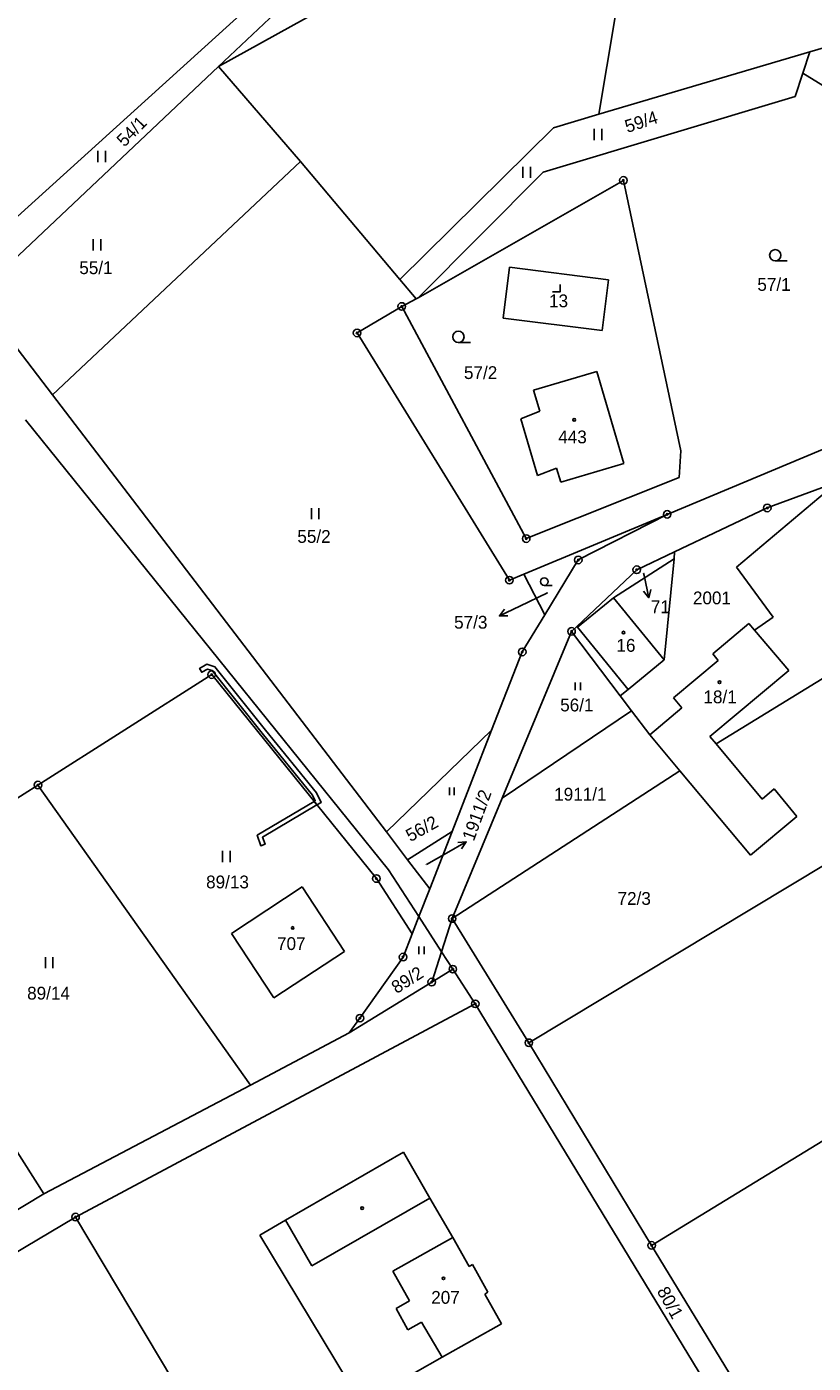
# Model space of a CAD drawing. Extents: x -445050 to -440454, y -1134563 to -1129741.
# Drawn here: x -441462.8 to -441358.3, y -1130247.4 to -1130069.9 of the extents above; entities that cross this region are included whole.
import ezdxf

# ---------------------------------------------------------------- set-up
doc = ezdxf.new("R2010")
doc.units = 0
for name, color, linetype in [('Vrstva 1', 7, 'Continuous'), ('Vrstva 16', 7, 'Continuous'), ('Vrstva 18', 7, 'Continuous'), ('Vrstva 19', 7, 'Continuous'), ('Vrstva 24', 7, 'Continuous'), ('Vrstva 25', 7, 'Continuous'), ('Vrstva 3', 7, 'Continuous'), ('Vrstva 30', 7, 'Continuous'), ('Vrstva 37', 7, 'Continuous'), ('Vrstva 4', 7, 'Continuous'), ('Vrstva 6', 7, 'Continuous')]:
    doc.layers.add(name, color=color, linetype=linetype)

msp = doc.modelspace()

# ---------------------------------------------------------------- linework, layer by layer
at = {"layer": 'Vrstva 1'}
for p, q in [((-441461.32, -1130170.56), (-441438.25, -1130155.89)), ((-441438.25, -1130155.89), (-441416.37, -1130182.98)), ((-441485.35, -1130185.84), (-441461.32, -1130170.56)), ((-441433.11, -1130210.4), (-441461.32, -1130170.56)), ((-441416.37, -1130182.98), (-441411.63, -1130190.33)), ((-441435.6, -1130190.26), (-441426.21, -1130184.1)), ((-441426.21, -1130184.1), (-441420.61, -1130192.66)), ((-441410.73, -1130188.03), (-441411.63, -1130190.33)), ((-441429.99, -1130198.8), (-441435.6, -1130190.26)), ((-441411.63, -1130190.33), (-441412.83, -1130193.4)), ((-441420.61, -1130192.66), (-441429.99, -1130198.8)), ((-441419.98, -1130203.47), (-441433.11, -1130210.4)), ((-441433.11, -1130210.4), (-441460.53, -1130224.86))]:
    msp.add_line(p, q, dxfattribs=at)
for points in [[(-441360.76, -1130079.1), (-441359.72, -1130076)], [(-441359.72, -1130076), (-441341.25, -1130087.41)], [(-441394.23, -1130089.18), (-441360.76, -1130079.1)], [(-441394.23, -1130089.18), (-441410.83, -1130105.86)], [(-441410.83, -1130105.86), (-441383.57, -1130090.26)], [(-441383.57, -1130090.26), (-441375.92, -1130126.16)], [(-441399.55, -1130108.54), (-441398.7, -1130101.8)], [(-441398.7, -1130101.8), (-441385.55, -1130103.45)], [(-441385.55, -1130103.45), (-441386.39, -1130110.19)], [(-441469.51, -1130105.5), (-441459.4, -1130118.73)], [(-441418.94, -1130110.52), (-441413.01, -1130107)], [(-441413.01, -1130107), (-441411.07, -1130105.99)], [(-441413.01, -1130107), (-441396.47, -1130137.84)], [(-441411.07, -1130105.99), (-441410.83, -1130105.86)], [(-441386.39, -1130110.19), (-441399.55, -1130108.54)], [(-441398.71, -1130143.35), (-441418.94, -1130110.52)], [(-441387.1, -1130115.63), (-441395.52, -1130118.1)], [(-441383.51, -1130127.88), (-441387.1, -1130115.63)], [(-441395.52, -1130118.1), (-441394.68, -1130120.93)], [(-441459.4, -1130118.73), (-441415.04, -1130176.77)], [(-441394.68, -1130120.93), (-441397.19, -1130121.93)], [(-441462.97, -1130122.08), (-441414.75, -1130181.81)], [(-441397.19, -1130121.93), (-441394.98, -1130129.46)], [(-441377.75, -1130134.61), (-441351.39, -1130123.59)], [(-441375.92, -1130126.16), (-441376.15, -1130129.73)], [(-441394.98, -1130129.46), (-441392.45, -1130128.47)], [(-441392.45, -1130128.47), (-441391.88, -1130130.32)], [(-441391.88, -1130130.32), (-441383.51, -1130127.88)], [(-441376.15, -1130129.73), (-441396.47, -1130137.84)], [(-441355.09, -1130130.3), (-441368.53, -1130141.61)], [(-441355.09, -1130130.3), (-441364.45, -1130133.76)], [(-441376.78, -1130139.6), (-441364.45, -1130133.76)], [(-441318.92, -1130132.99), (-441371.23, -1130165.11)], [(-441377.75, -1130134.61), (-441396.77, -1130142.54)], [(-441389.56, -1130140.67), (-441377.75, -1130134.61)], [(-441393.99, -1130147.95), (-441389.56, -1130140.67)], [(-441384.88, -1130145.69), (-441376.84, -1130140.52)], [(-441376.78, -1130139.6), (-441381.8, -1130141.97)], [(-441378.14, -1130153.94), (-441376.84, -1130140.52)], [(-441376.78, -1130139.6), (-441376.84, -1130140.52)], [(-441396.77, -1130142.54), (-441398.71, -1130143.35)], [(-441396.77, -1130142.54), (-441393.99, -1130147.95)], [(-441381.8, -1130141.97), (-441389.76, -1130149.5)], [(-441368.53, -1130141.61), (-441363.66, -1130148.25)], [(-441389.67, -1130149.61), (-441384.88, -1130145.69)], [(-441397, -1130152.88), (-441393.99, -1130147.95)], [(-441363.66, -1130148.25), (-441366.15, -1130150.01)], [(-441390.45, -1130150.15), (-441399.66, -1130172.29)], [(-441389.76, -1130149.5), (-441390.45, -1130150.15)], [(-441390.45, -1130150.15), (-441383.98, -1130158.72)], [(-441389.67, -1130149.61), (-441389.76, -1130149.5)], [(-441371.68, -1130153.14), (-441366.91, -1130149.12)], [(-441366.91, -1130149.12), (-441366.15, -1130150.01)], [(-441366.15, -1130150.01), (-441361.6, -1130155.35)], [(-441401.07, -1130163.29), (-441397, -1130152.88)], [(-441370.99, -1130154), (-441371.68, -1130153.14)], [(-441378.14, -1130153.94), (-441382.93, -1130157.86)], [(-441376.91, -1130158.99), (-441370.99, -1130154)], [(-441361.6, -1130155.35), (-441372.07, -1130164.1)], [(-441383.98, -1130158.72), (-441382.93, -1130157.86)], [(-441382.47, -1130160.71), (-441383.98, -1130158.72)], [(-441375.79, -1130160.32), (-441376.91, -1130158.99)], [(-441382.47, -1130160.71), (-441399.66, -1130172.29)], [(-441380.07, -1130163.89), (-441382.47, -1130160.71)], [(-441380.07, -1130163.89), (-441375.79, -1130160.32)], [(-441415.04, -1130176.77), (-441401.07, -1130163.29)], [(-441406.32, -1130176.73), (-441401.07, -1130163.29)], [(-441376.07, -1130168.66), (-441380.07, -1130163.89)], [(-441372.07, -1130164.1), (-441371.23, -1130165.11)], [(-441371.23, -1130165.11), (-441365.15, -1130172.43)], [(-441376.07, -1130168.66), (-441406.31, -1130188.29)], [(-441366.69, -1130179.87), (-441376.07, -1130168.66)], [(-441365.15, -1130172.43), (-441363.53, -1130171.07)], [(-441363.53, -1130171.07), (-441360.51, -1130174.73)], [(-441399.66, -1130172.29), (-441406.31, -1130188.29)], [(-441360.51, -1130174.73), (-441366.69, -1130179.87)], [(-441415.04, -1130176.77), (-441412.22, -1130180.49)], [(-441406.32, -1130176.73), (-441412.22, -1130180.49)], [(-441409.29, -1130184.35), (-441406.32, -1130176.73)], [(-441410.73, -1130188.03), (-441414.75, -1130181.81)], [(-441412.22, -1130180.49), (-441409.29, -1130184.35)], [(-441410.73, -1130188.03), (-441409.29, -1130184.35)], [(-441460.53, -1130224.86), (-441485.35, -1130185.84)], [(-441410.73, -1130188.03), (-441407.72, -1130192.69)], [(-441406.31, -1130188.29), (-441407.72, -1130192.69)], [(-441406.31, -1130188.29), (-441396.12, -1130204.79)], [(-441407.72, -1130192.69), (-441406.22, -1130195.01)], [(-441418.56, -1130201.52), (-441412.83, -1130193.4)], [(-441406.22, -1130195.01), (-441409.02, -1130196.73)], [(-441403.24, -1130199.62), (-441406.22, -1130195.01)], [(-441409.02, -1130196.73), (-441419.98, -1130203.47)], [(-441403.24, -1130199.62), (-441456.33, -1130227.93)], [(-441403.24, -1130199.62), (-441353.13, -1130282.09)], [(-441418.56, -1130201.52), (-441419.98, -1130203.47)], [(-441379.81, -1130231.69), (-441396.12, -1130204.79)], [(-441412.78, -1130219.31), (-441428.46, -1130228.36)], [(-441409.26, -1130225.41), (-441412.78, -1130219.31)], [(-441460.53, -1130224.86), (-441465.68, -1130227.95)], [(-441409.26, -1130225.41), (-441406.23, -1130230.65)], [(-441456.33, -1130227.93), (-441507.09, -1130258.08)], [(-441456.33, -1130227.93), (-441408.04, -1130308.81)], [(-441428.46, -1130228.36), (-441431.87, -1130230.33)], [(-441431.87, -1130230.33), (-441418.41, -1130252.66)], [(-441406.23, -1130230.65), (-441404.06, -1130234.5)], [(-441379.81, -1130231.69), (-441350.11, -1130280.47)], [(-441404.06, -1130234.5), (-441403.62, -1130234.25)], [(-441403.62, -1130234.25), (-441401.55, -1130237.93)], [(-441401.55, -1130237.93), (-441401.98, -1130238.17)], [(-441401.98, -1130238.17), (-441399.76, -1130242.11)], [(-441399.76, -1130242.11), (-441407.63, -1130246.56)], [(-441407.63, -1130246.56), (-441418.41, -1130252.66)]]:
    msp.add_lwpolyline(points, dxfattribs=at)
at = {"layer": 'Vrstva 16'}
for p, q in [((-441380.81, -1130142.75), (-441380.18, -1130145.68)), ((-441397.32, -1130146.79), (-441400.03, -1130148.09)), ((-441407.04, -1130179.59), (-441404.43, -1130178.11))]:
    msp.add_line(p, q, dxfattribs=at)
for points in [[(-441380.88, -1130142.42), (-441380.81, -1130142.75)], [(-441379.9, -1130144.6), (-441380.18, -1130145.68), (-441380.88, -1130144.81)], [(-441393.66, -1130145.04), (-441397.32, -1130146.79)], [(-441398.91, -1130148.1), (-441400.03, -1130148.09), (-441399.34, -1130147.2)], [(-441405.55, -1130178.17), (-441404.43, -1130178.11), (-441405.05, -1130179.04)], [(-441409.72, -1130181.12), (-441407.04, -1130179.59)]]:
    msp.add_lwpolyline(points, dxfattribs=at)
at = {"layer": 'Vrstva 24'}
for centre, radius in [((-441383.57, -1130090.26), 0.5), ((-441383.57, -1130090.26), 0.1), ((-441413.01, -1130107), 0.5), ((-441413.01, -1130107), 0.1), ((-441418.94, -1130110.52), 0.5), ((-441418.94, -1130110.52), 0.1), ((-441377.75, -1130134.61), 0.5), ((-441364.45, -1130133.76), 0.5), ((-441364.45, -1130133.76), 0.1), ((-441377.75, -1130134.61), 0.1), ((-441396.47, -1130137.84), 0.5), ((-441396.47, -1130137.84), 0.1), ((-441389.56, -1130140.67), 0.5), ((-441389.56, -1130140.67), 0.1), ((-441398.71, -1130143.35), 0.5), ((-441381.8, -1130141.97), 0.5), ((-441381.8, -1130141.97), 0.1), ((-441398.71, -1130143.35), 0.1), ((-441390.45, -1130150.15), 0.5), ((-441390.45, -1130150.15), 0.1), ((-441397, -1130152.88), 0.5), ((-441397, -1130152.88), 0.1), ((-441438.25, -1130155.89), 0.5), ((-441438.25, -1130155.89), 0.1), ((-441461.32, -1130170.56), 0.5), ((-441461.32, -1130170.56), 0.1), ((-441416.37, -1130182.98), 0.5), ((-441416.37, -1130182.98), 0.1), ((-441406.31, -1130188.29), 0.5), ((-441406.31, -1130188.29), 0.1), ((-441412.83, -1130193.4), 0.5), ((-441412.83, -1130193.4), 0.1), ((-441406.22, -1130195.01), 0.5), ((-441409.02, -1130196.73), 0.5), ((-441406.22, -1130195.01), 0.1), ((-441409.02, -1130196.73), 0.1), ((-441403.24, -1130199.62), 0.5), ((-441403.24, -1130199.62), 0.1), ((-441418.56, -1130201.52), 0.5), ((-441418.56, -1130201.52), 0.1), ((-441396.12, -1130204.79), 0.5), ((-441396.12, -1130204.79), 0.1), ((-441456.33, -1130227.93), 0.5), ((-441456.33, -1130227.93), 0.1), ((-441379.81, -1130231.69), 0.5), ((-441379.81, -1130231.69), 0.1)]:
    msp.add_circle(centre, radius, dxfattribs=at)
at = {"layer": 'Vrstva 25'}
for p, q in [((-441387.44, -1130084.93), (-441387.44, -1130083.43)), ((-441386.44, -1130084.93), (-441386.44, -1130083.43)), ((-441453.35, -1130087.83), (-441453.35, -1130086.33)), ((-441452.35, -1130087.83), (-441452.35, -1130086.33)), ((-441396.9, -1130089.94), (-441396.9, -1130088.44)), ((-441395.9, -1130089.94), (-441395.9, -1130088.44)), ((-441453.97, -1130099.57), (-441453.97, -1130098.07)), ((-441452.97, -1130099.57), (-441452.97, -1130098.07)), ((-441363.4, -1130100.95), (-441361.8, -1130100.95)), ((-441405.48, -1130111.79), (-441403.88, -1130111.79)), ((-441425.01, -1130135.27), (-441425.01, -1130133.77)), ((-441424.01, -1130135.27), (-441424.01, -1130133.77)), ((-441394.08, -1130144.05), (-441393.01, -1130144.05)), ((-441389.95, -1130157.96), (-441389.95, -1130156.96)), ((-441389.28, -1130157.96), (-441389.28, -1130156.96)), ((-441406.68, -1130171.89), (-441406.68, -1130170.89)), ((-441406.02, -1130171.89), (-441406.02, -1130170.89)), ((-441436.8, -1130180.82), (-441436.8, -1130179.32)), ((-441435.8, -1130180.82), (-441435.8, -1130179.32)), ((-441410.72, -1130193.01), (-441410.72, -1130192.01)), ((-441410.04, -1130193.01), (-441410.04, -1130192.01)), ((-441460.34, -1130194.9), (-441460.34, -1130193.4)), ((-441459.34, -1130194.9), (-441459.34, -1130193.4))]:
    msp.add_line(p, q, dxfattribs=at)
msp.add_lwpolyline([(-441392.97, -1130105.08), (-441391.97, -1130105.08), (-441391.97, -1130104.08)], dxfattribs=at)
for centre, radius in [((-441363.4, -1130100.2), 0.75), ((-441405.48, -1130111.04), 0.75), ((-441390.09, -1130122.06), 0.175), ((-441394.08, -1130143.55), 0.503), ((-441383.54, -1130150.32), 0.175), ((-441370.79, -1130156.91), 0.175), ((-441427.49, -1130189.54), 0.175), ((-441418.27, -1130226.75), 0.175), ((-441407.45, -1130236.07), 0.175)]:
    msp.add_circle(centre, radius, dxfattribs=at)
at = {"layer": 'Vrstva 3'}
for points in [[(-441387.1, -1130115.63), (-441395.52, -1130118.1)], [(-441383.51, -1130127.88), (-441387.1, -1130115.63)], [(-441395.52, -1130118.1), (-441394.68, -1130120.93)], [(-441394.68, -1130120.93), (-441397.19, -1130121.93)], [(-441397.19, -1130121.93), (-441394.98, -1130129.46)], [(-441394.98, -1130129.46), (-441392.45, -1130128.47)], [(-441392.45, -1130128.47), (-441391.88, -1130130.32)], [(-441391.88, -1130130.32), (-441383.51, -1130127.88)], [(-441389.67, -1130149.61), (-441384.88, -1130145.69)], [(-441384.88, -1130145.69), (-441378.14, -1130153.94)], [(-441382.93, -1130157.86), (-441389.67, -1130149.61)], [(-441371.68, -1130153.14), (-441366.91, -1130149.12)], [(-441366.91, -1130149.12), (-441366.15, -1130150.01)], [(-441366.15, -1130150.01), (-441361.6, -1130155.35)], [(-441370.99, -1130154), (-441371.68, -1130153.14)], [(-441378.14, -1130153.94), (-441382.93, -1130157.86)], [(-441376.91, -1130158.99), (-441370.99, -1130154)], [(-441361.6, -1130155.35), (-441372.07, -1130164.1)], [(-441375.79, -1130160.32), (-441376.91, -1130158.99)], [(-441380.07, -1130163.89), (-441375.79, -1130160.32)], [(-441376.07, -1130168.66), (-441380.07, -1130163.89)], [(-441372.07, -1130164.1), (-441371.23, -1130165.11)], [(-441371.23, -1130165.11), (-441365.15, -1130172.43)], [(-441366.69, -1130179.87), (-441376.07, -1130168.66)], [(-441365.15, -1130172.43), (-441363.53, -1130171.07)], [(-441363.53, -1130171.07), (-441360.51, -1130174.73)], [(-441360.51, -1130174.73), (-441366.69, -1130179.87)], [(-441435.6, -1130190.26), (-441426.21, -1130184.1)], [(-441426.21, -1130184.1), (-441420.61, -1130192.66)], [(-441429.99, -1130198.8), (-441435.6, -1130190.26)], [(-441420.61, -1130192.66), (-441429.99, -1130198.8)], [(-441414.19, -1130235.14), (-441406.23, -1130230.65)], [(-441406.23, -1130230.65), (-441404.06, -1130234.5)], [(-441411.97, -1130239.08), (-441414.19, -1130235.14)], [(-441404.06, -1130234.5), (-441403.62, -1130234.25)], [(-441403.62, -1130234.25), (-441401.55, -1130237.93)], [(-441401.55, -1130237.93), (-441401.98, -1130238.17)], [(-441401.98, -1130238.17), (-441399.76, -1130242.11)], [(-441413.76, -1130240.09), (-441411.97, -1130239.08)], [(-441412.18, -1130242.89), (-441413.76, -1130240.09)], [(-441410.39, -1130241.88), (-441412.18, -1130242.89)], [(-441407.63, -1130246.56), (-441410.39, -1130241.88)], [(-441399.76, -1130242.11), (-441407.63, -1130246.56)]]:
    msp.add_lwpolyline(points, dxfattribs=at)
at = {"layer": 'Vrstva 30'}
for points in [[(-441431.54, -1130163.67), (-441438.17, -1130155.37), (-441438.82, -1130155.17), (-441439.57, -1130155.59), (-441439.86, -1130155.07), (-441438.88, -1130154.53), (-441437.81, -1130154.85), (-441431.08, -1130163.29), (-441424.32, -1130171.59), (-441423.71, -1130172.88), (-441424.26, -1130173.21), (-441424.65, -1130172.73), (-441424.49, -1130172.64), (-441424.84, -1130171.91), (-441431.54, -1130163.67)], [(-441424.26, -1130173.21), (-441431.48, -1130177.48), (-441431.16, -1130178.42), (-441431.72, -1130178.62), (-441432.2, -1130177.22), (-441424.65, -1130172.73), (-441424.26, -1130173.21)]]:
    msp.add_lwpolyline(points, dxfattribs=at)
at = {"layer": 'Vrstva 37'}
for centre in [(-441390.09, -1130122.06), (-441383.54, -1130150.32), (-441370.79, -1130156.91), (-441427.49, -1130189.54), (-441407.45, -1130236.07)]:
    msp.add_circle(centre, 0.175, dxfattribs=at)
at = {"layer": 'Vrstva 4'}
for points in [[(-441384.88, -1130145.69), (-441378.14, -1130153.94)], [(-441382.93, -1130157.86), (-441389.67, -1130149.61)], [(-441407.72, -1130192.69), (-441409.02, -1130196.73)], [(-441424.96, -1130234.42), (-441409.26, -1130225.41)], [(-441428.46, -1130228.36), (-441424.96, -1130234.42)], [(-441414.19, -1130235.14), (-441406.23, -1130230.65)], [(-441411.97, -1130239.08), (-441414.19, -1130235.14)], [(-441413.76, -1130240.09), (-441411.97, -1130239.08)], [(-441412.18, -1130242.89), (-441413.76, -1130240.09)], [(-441410.39, -1130241.88), (-441412.18, -1130242.89)], [(-441407.63, -1130246.56), (-441410.39, -1130241.88)]]:
    msp.add_lwpolyline(points, dxfattribs=at)
at = {"layer": 'Vrstva 6'}
for points in [[(-441373.15, -1129999.93), (-441386.84, -1130081.48)], [(-441466.44, -1130097.18), (-441424.59, -1130059.3)], [(-441437.35, -1130075.13), (-441421.54, -1130060.2)], [(-441423.96, -1130067.73), (-441437.35, -1130075.13)], [(-441350.63, -1130070.78), (-441358.79, -1130073.19)], [(-441358.79, -1130073.19), (-441386.84, -1130081.48)], [(-441359.72, -1130076), (-441358.79, -1130073.19)], [(-441469.51, -1130105.5), (-441437.35, -1130075.13)], [(-441437.35, -1130075.13), (-441426.46, -1130087.77)], [(-441386.84, -1130081.48), (-441392.86, -1130083.3)], [(-441392.86, -1130083.3), (-441413.25, -1130103.44)], [(-441426.46, -1130087.77), (-441459.4, -1130118.73)], [(-441426.46, -1130087.77), (-441413.25, -1130103.44)], [(-441413.25, -1130103.44), (-441411.07, -1130105.99)], [(-441396.12, -1130204.79), (-441316.97, -1130157.17)], [(-441317.36, -1130193.53), (-441379.81, -1130231.69)]]:
    msp.add_lwpolyline(points, dxfattribs=at)

# ---------------------------------------------------------------- texts
at = {"layer": 'Vrstva 16'}
for s, p in [('71', (-441379.92, -1130147.74)), ('57/3', (-441406.05, -1130149.79))]:
    msp.add_text(s, height=1.7, dxfattribs=at).set_placement(p)
msp.add_text('1911/2', height=1.7, rotation=69.8755, dxfattribs=at).set_placement((-441403.43, -1130178.11))
at = {"layer": 'Vrstva 18'}
for s, rotation, p in [('54/1', 45.4356, (-441449.83, -1130085.91)), ('59/4', 18.1071, (-441383.04, -1130083.97)), ('56/2', 28.9737, (-441411.86, -1130178.16)), ('89/2', 32.1921, (-441413.69, -1130198.33)), ('80/1', 298.7892, (-441379.16, -1130237.76))]:
    msp.add_text(s, height=1.7, rotation=rotation, dxfattribs=at).set_placement(p)
for s, height, p in [('55/1', 1.7, (-441455.83, -1130102.71)), ('57/1', 1.7, (-441365.77, -1130104.93)), ('57/2', 1.7, (-441404.74, -1130116.64)), ('55/2', 1.7, (-441426.87, -1130138.4)), ('71', 0.1, (-441380.93, -1130142.42)), ('2001', 1.7, (-441374.33, -1130146.56)), ('57/3', 0.1, (-441393.81, -1130145.04)), ('56/1', 1.7, (-441391.96, -1130160.78)), ('1911/1', 1.7, (-441392.76, -1130172.63)), ('1911/2', 0.1, (-441409.9, -1130181.12)), ('89/13', 1.7, (-441438.99, -1130184.28)), ('72/3', 1.7, (-441384.34, -1130186.47)), ('89/14', 1.7, (-441462.76, -1130199.05))]:
    msp.add_text(s, height=height, dxfattribs=at).set_placement(p)
at = {"layer": 'Vrstva 19'}
for s, p in [('13', (-441393.44, -1130107.11)), ('443', (-441392.22, -1130125.18)), ('16', (-441384.49, -1130152.86)), ('18/1', (-441372.93, -1130159.7)), ('707', (-441429.57, -1130192.47)), ('207', (-441409.09, -1130239.45))]:
    msp.add_text(s, height=1.7, dxfattribs=at).set_placement(p)

doc.saveas('drawing.dxf')
